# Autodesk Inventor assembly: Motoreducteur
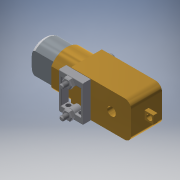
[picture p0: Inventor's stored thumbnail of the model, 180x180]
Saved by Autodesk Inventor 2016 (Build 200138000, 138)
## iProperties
Created: 2018-03
Part Number: Motoreducteur
Material: Générique
Document SubType Name: Assembly
Designer: Bruno
Author: Bruno
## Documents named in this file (6)
- D:\Cours\1-Cours-2017-18\2SI\projet\Inventor\Motoreducteur.iam
- D:\Cours\1-Cours-2017-18\2SI\projet\Inventor\reducteur.ipt
- D:\Cours\1-Cours-2017-18\2SI\projet\Inventor\moteur.ipt
- D:\Cours\1-Cours-2017-18\2SI\projet\Inventor\vis-M2.8.ipt
- D:\Cours\1-Cours-2017-18\2SI\projet\Inventor\Attache-moteur.ipt
- D:\Cours\1-Cours-2017-18\2SI\projet\Inventor\ecrou-M2.8.ipt
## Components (7 placed, 5 different names)
1. reducteur:1 — Placage:1, Placage:2, Angle:1, Placage:3, Placage:4, Placage:6, Placage:7, Placage:8, Angle:2
2. moteur:1 — Placage:1, Placage:2, Angle:1
3. vis-M2.8:1 — Placage:5, Placage:8, Placage:9
4. vis-M2.8:2 — Placage:6, Placage:7, Placage:10
5. Attache-moteur:1 — Placage:3, Placage:4, Placage:5, Angle:2, Placage:11, Placage:12
6. ecrou-M2.8:1 — Placage:10, Placage:12
7. ecrou-M2.8:2 — Placage:9, Placage:11
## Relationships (14: Mate 12, Angle 2)
- Placage:1 [Mate]: reducteur:1 ↔ moteur:1
- Placage:2 [Mate]: reducteur:1 ↔ moteur:1
- Angle:1: reducteur:1 ↔ moteur:1
- Placage:3 [Mate]: reducteur:1 ↔ Attache-moteur:1
- Placage:4 [Mate]: reducteur:1 ↔ Attache-moteur:1
- Placage:5 [Mate]: vis-M2.8:1 ↔ Attache-moteur:1
- Placage:6 [Mate]: reducteur:1 ↔ vis-M2.8:2
- Placage:7 [Mate]: reducteur:1 ↔ vis-M2.8:2
- Placage:8 [Mate]: reducteur:1 ↔ vis-M2.8:1
- Angle:2: reducteur:1 ↔ Attache-moteur:1
- Placage:9 [Mate]: vis-M2.8:1 ↔ ecrou-M2.8:2
- Placage:10 [Mate]: vis-M2.8:2 ↔ ecrou-M2.8:1
- Placage:11 [Mate]: Attache-moteur:1 ↔ ecrou-M2.8:2
- Placage:12 [Mate]: Attache-moteur:1 ↔ ecrou-M2.8:1
